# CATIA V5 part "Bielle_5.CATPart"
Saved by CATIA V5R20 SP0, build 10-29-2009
Part number: Bielle_5
Bounding box of the stored display mesh (mm): x 0 to 1, y 68 to 72, z 20.5 to 39.5
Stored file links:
  C:\Users\J\IAO_2012_jgossard\Bielle_5.CATPart
  C:\Users\J\IAO_2012_jgossard\jgossard.CATProduct
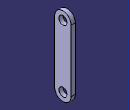
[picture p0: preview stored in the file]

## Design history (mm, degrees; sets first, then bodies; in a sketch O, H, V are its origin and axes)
Set1
  Plane1 "Plan_ref": linked copy from another document
  Point1 "Point_E": linked copy from another document
  Point2 "Point_F": linked copy from another document
  Point3 "Point_D": linked copy from another document
  Line1 "Corps_bati": linked copy from another document
Body1 (main body)
  Sketch1 on Plane1, origin (0, 0, 0), H (0, 1, 0), V (0, 0, 1)
    construction line L1 (70, 37.5) -> (70, 22.5)
    point P1 (70, 37.5)
    point P2 (70, 22.5)
    line L2 (72, 37.5) -> (72, 22.5)
    line L3 (68, 22.5) -> (68, 37.5)
    arc A1 centre (70, 22.5) radius 2 from (72, 22.5) to (68, 22.5) cw
    arc A2 centre (70, 37.5) radius 2 from (68, 37.5) to (72, 37.5) cw
    reference projected point E1 (70, 37.5) from Point1
    reference projected point E2 (70, 22.5) from Point2
    distance L1 L2 = 2
    vertical: L1 V
    tangency: A1 L2, A2 L2, A1 L3, A2 L3
    coincidence: P1 E1, P2 E2
  Pad1: profile Sketch1, direction (1, 0, 0), length 1
  Sketch2 on end face of Pad1, origin (1, 69.4385, 26.4906), H (0, 1, 0), V (0, 0, 1)
    point P1 (0.5615, 11.0094)
    reference projected point E1 (0.5615, 11.0094) from Point1
    coincidence: P1 E1
  Hole1: placed by Sketch2, at (1, 70, 37.5) direction (-1, 0, 0), diameter 2, through (limit type 6)
  Sketch3 on end face of Pad1, origin (1, 70.7501, 18.6201), H (0, 1, 0), V (0, 0, 1)
    point P1 (-0.7501, 3.8799)
    reference projected point E1 (-0.7501, 3.8799) from Point2
    coincidence: P1 E1
  Hole2: placed by Sketch3, at (1, 70, 22.5) direction (-1, 0, 0), diameter 2, through (limit type 6)
  Line2 "Corps_bati": stored without definition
